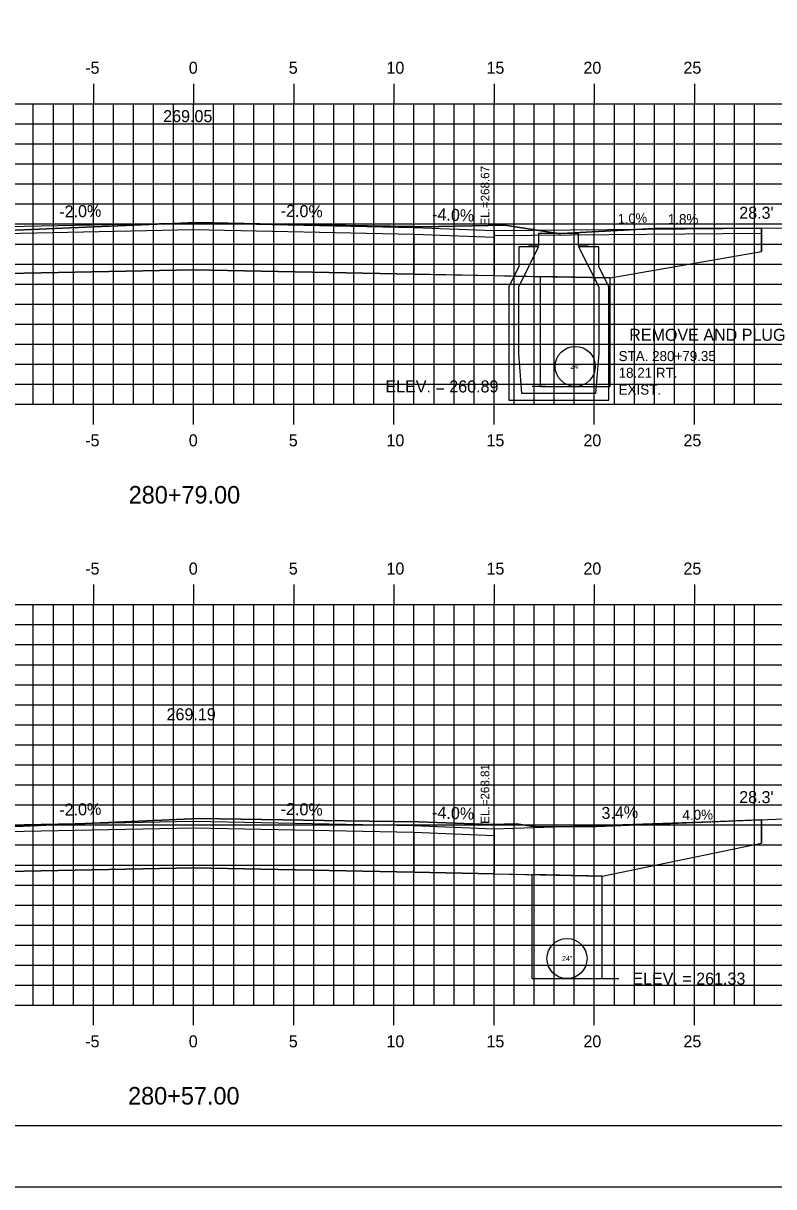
# Model space of a CAD drawing. Extents: x 855344 to 855514, y 366268 to 366378.
# Drawn here: x 855418.6 to 855456.1, y 366268.2 to 366326.3 of the extents above; entities that cross this region are included whole.
import ezdxf

# ---------------------------------------------------------------- set-up
doc = ezdxf.new("R2010")
doc.units = 0
for name, color, linetype in [('ANNOTATION', 7, 'Continuous'), ('BORDER', 7, 'Continuous'), ('D_Roadway_Centerline_Text', 7, 'Continuous'), ('D_Roadway_Drive_Gravel_RT', 7, 'Continuous'), ('D_Roadway_Drive_SubGrade', 7, 'Continuous'), ('D_Roadway_Edge_Shoulder', 7, 'Continuous'), ('D_Roadway_SubGrade', 7, 'Continuous'), ('D_Text_Monospaced', 7, 'Continuous'), ('D_Text_Standard', 7, 'Continuous'), ('H_V ANNOTATION', 7, 'Continuous'), ('JUNK COM EXC', 7, 'Continuous'), ('junk strct exc', 7, 'Continuous'), ('MAJOR', 7, 'Continuous'), ('MINOR', 7, 'Continuous'), ('PDRAIN', 7, 'Continuous'), ('PLOT BOUNDARY', 7, 'Continuous'), ('S_Drainage_CB', 7, 'Continuous'), ('S_Roadway_Centerline', 7, 'Continuous')]:
    doc.layers.add(name, color=color, linetype=linetype)

msp = doc.modelspace()

# ---------------------------------------------------------------- linework, layer by layer
at = {"layer": 'BORDER'}
msp.add_line((855352.11, 366271.236), (855512.11, 366271.236), dxfattribs=at)
at = {"layer": 'D_Roadway_Drive_Gravel_RT'}
for p, q in [((855442.11, 366315.908), (855455.458, 366316.033)), ((855442.11, 366315.658), (855455.458, 366315.783)), ((855442.107, 366286.048), (855455.456, 366286.494))]:
    msp.add_line(p, q, dxfattribs=at)
at = {"layer": 'D_Roadway_Drive_SubGrade'}
for p, q in [((855455.458, 366316.033), (855455.458, 366314.866)), ((855447.908, 366313.54), (855455.458, 366314.866)), ((855442.109, 366313.656), (855447.908, 366313.54)), ((855455.456, 366286.494), (855455.456, 366285.327)), ((855447.496, 366283.687), (855455.456, 366285.327)), ((855442.107, 366283.795), (855447.496, 366283.687))]:
    msp.add_line(p, q, dxfattribs=at)
at = {"layer": 'D_Roadway_Edge_Shoulder'}
for p, q in [((855442.107, 366315.908), (855442.11, 366315.575)), ((855442.11, 366315.908), (855442.109, 366315.576)), ((855442.107, 366286.048), (855442.11, 366285.547)), ((855442.107, 366286.048), (855442.107, 366285.715))]:
    msp.add_line(p, q, dxfattribs=at)
for points in [[(855410.364, 366315.839), (855416.11, 366316.069), (855427.11, 366316.288), (855438.11, 366316.068), (855442.107, 366315.908)], [(855408.764, 366285.915), (855416.11, 366286.208), (855427.11, 366286.428), (855438.11, 366286.208), (855442.107, 366286.048)]]:
    msp.add_lwpolyline(points, dxfattribs=at)
at = {"layer": 'D_Roadway_SubGrade'}
for points in [[(855416.11, 366313.735), (855416.11, 366315.735), (855427.11, 366315.955), (855438.11, 366315.735), (855438.11, 366313.735), (855427.11, 366313.955)], [(855438.11, 366315.735), (855442.11, 366315.575), (855442.11, 366313.655), (855438.11, 366313.735)], [(855416.11, 366283.875), (855416.11, 366285.875), (855427.11, 366286.095), (855438.11, 366285.875), (855438.11, 366283.875), (855427.11, 366284.095)], [(855438.11, 366285.875), (855442.11, 366285.715), (855442.11, 366283.795), (855438.11, 366283.875)]]:
    msp.add_lwpolyline(points, close=True, dxfattribs=at)
at = {"layer": 'D_Text_Standard'}
for points in [[(855444.408, 366308.126), (855444.687, 366308.126), (855444.007, 366308.126)], [(855447.496, 366278.566), (855447.645, 366278.566), (855448.325, 366278.566)]]:
    msp.add_lwpolyline(points, dxfattribs=at)
at = {"layer": 'JUNK COM EXC'}
for points in [[(855442.11, 366313.656), (855443.109, 366313.636), (855447.908, 366313.54), (855455.458, 366314.866), (855455.458, 366316.033), (855450.115, 366316.007), (855445.453, 366315.764), (855445.301, 366315.765), (855442.641, 366316.173), (855438.522, 366316.091), (855438.043, 366316.107), (855433.603, 366316.181), (855427.262, 366316.303), (855418.219, 366315.925), (855416.377, 366315.798), (855415.114, 366315.783), (855411.326, 366315.64), (855409.364, 366315.641), (855409.364, 366313.6), (855410.364, 366313.62), (855416.11, 366313.735), (855427.11, 366313.955), (855438.11, 366313.735), (855440.11, 366313.695)], [(855455.456, 366286.494), (855448.857, 366286.219), (855446.795, 366286.149), (855444.06, 366286.162), (855443.249, 366286.287), (855441.994, 366286.262), (855438.341, 366286.386), (855434.651, 366286.447), (855427.383, 366286.558), (855424.003, 366286.406), (855416.618, 366286.097), (855413.068, 366285.862), (855411.293, 366285.775), (855408.987, 366285.898), (855407.764, 366285.942), (855407.764, 366283.708), (855408.764, 366283.728), (855416.11, 366283.875), (855427.11, 366284.095), (855438.11, 366283.875), (855442.11, 366283.795), (855443.107, 366283.775), (855447.496, 366283.687), (855455.456, 366285.327)]]:
    msp.add_lwpolyline(points, close=True, dxfattribs=at)
at = {"layer": 'junk strct exc'}
for points in [[(855444.408, 366313.61), (855444.408, 366308.126), (855447.908, 366308.126), (855447.908, 366313.54)], [(855443.996, 366283.757), (855443.996, 366278.566), (855447.496, 366278.566), (855447.496, 366283.687)]]:
    msp.add_lwpolyline(points, close=True, dxfattribs=at)
at = {"layer": 'MAJOR'}
for p, q in [((855422.11, 366323.238), (855422.11, 366322.236)), ((855427.11, 366323.238), (855427.11, 366322.236)), ((855432.11, 366323.238), (855432.11, 366322.236)), ((855437.11, 366323.238), (855437.11, 366322.236)), ((855442.11, 366323.238), (855442.11, 366322.236)), ((855447.11, 366323.238), (855447.11, 366322.236)), ((855452.11, 366323.238), (855452.11, 366322.236)), ((855357.11, 366322.236), (855497.11, 366322.236)), ((855357.11, 366322.236), (855497.11, 366322.236)), ((855422.11, 366307.236), (855422.11, 366322.236)), ((855427.11, 366307.236), (855427.11, 366322.236)), ((855432.11, 366307.236), (855432.11, 366322.236)), ((855437.11, 366307.236), (855437.11, 366322.236)), ((855442.11, 366307.236), (855442.11, 366322.236)), ((855447.11, 366307.236), (855447.11, 366322.236)), ((855452.11, 366307.236), (855452.11, 366322.236)), ((855357.11, 366317.236), (855497.11, 366317.236)), ((855357.11, 366312.236), (855497.11, 366312.236)), ((855357.11, 366307.236), (855497.11, 366307.236)), ((855357.11, 366307.236), (855497.11, 366307.236)), ((855422.11, 366306.234), (855422.11, 366307.236)), ((855427.11, 366306.234), (855427.11, 366307.236)), ((855432.11, 366306.234), (855432.11, 366307.236)), ((855437.11, 366306.234), (855437.11, 366307.236)), ((855442.11, 366306.234), (855442.11, 366307.236)), ((855447.11, 366306.234), (855447.11, 366307.236)), ((855452.11, 366306.234), (855452.11, 366307.236)), ((855422.11, 366298.238), (855422.11, 366297.236)), ((855427.11, 366298.238), (855427.11, 366297.236)), ((855432.11, 366298.238), (855432.11, 366297.236)), ((855437.11, 366298.238), (855437.11, 366297.236)), ((855442.11, 366298.238), (855442.11, 366297.236)), ((855447.11, 366298.238), (855447.11, 366297.236)), ((855452.11, 366298.238), (855452.11, 366297.236)), ((855357.11, 366297.236), (855497.11, 366297.236)), ((855357.11, 366297.236), (855497.11, 366297.236)), ((855422.11, 366277.236), (855422.11, 366297.236)), ((855427.11, 366277.236), (855427.11, 366297.236)), ((855432.11, 366277.236), (855432.11, 366297.236)), ((855437.11, 366277.236), (855437.11, 366297.236)), ((855442.11, 366277.236), (855442.11, 366297.236)), ((855447.11, 366277.236), (855447.11, 366297.236)), ((855452.11, 366277.236), (855452.11, 366297.236)), ((855357.11, 366292.236), (855497.11, 366292.236)), ((855357.11, 366287.236), (855497.11, 366287.236)), ((855357.11, 366282.236), (855497.11, 366282.236)), ((855357.11, 366277.236), (855497.11, 366277.236)), ((855357.11, 366277.236), (855497.11, 366277.236)), ((855422.11, 366276.234), (855422.11, 366277.236)), ((855427.11, 366276.234), (855427.11, 366277.236)), ((855432.11, 366276.234), (855432.11, 366277.236)), ((855437.11, 366276.234), (855437.11, 366277.236)), ((855442.11, 366276.234), (855442.11, 366277.236)), ((855447.11, 366276.234), (855447.11, 366277.236)), ((855452.11, 366276.234), (855452.11, 366277.236))]:
    msp.add_line(p, q, dxfattribs=at)
at = {"layer": 'MINOR'}
for p, q in [((855419.11, 366307.236), (855419.11, 366322.236)), ((855420.11, 366307.236), (855420.11, 366322.236)), ((855421.11, 366307.236), (855421.11, 366322.236)), ((855423.11, 366307.236), (855423.11, 366322.236)), ((855424.11, 366307.236), (855424.11, 366322.236)), ((855425.11, 366307.236), (855425.11, 366322.236)), ((855426.11, 366307.236), (855426.11, 366322.236)), ((855428.11, 366307.236), (855428.11, 366322.236)), ((855429.11, 366307.236), (855429.11, 366322.236)), ((855430.11, 366307.236), (855430.11, 366322.236)), ((855431.11, 366307.236), (855431.11, 366322.236)), ((855433.11, 366307.236), (855433.11, 366322.236)), ((855434.11, 366307.236), (855434.11, 366322.236)), ((855435.11, 366307.236), (855435.11, 366322.236)), ((855436.11, 366307.236), (855436.11, 366322.236)), ((855438.11, 366307.236), (855438.11, 366322.236)), ((855439.11, 366307.236), (855439.11, 366322.236)), ((855440.11, 366307.236), (855440.11, 366322.236)), ((855441.11, 366307.236), (855441.11, 366322.236)), ((855443.11, 366307.236), (855443.11, 366322.236)), ((855444.11, 366307.236), (855444.11, 366322.236)), ((855445.11, 366307.236), (855445.11, 366322.236)), ((855446.11, 366307.236), (855446.11, 366322.236)), ((855448.11, 366307.236), (855448.11, 366322.236)), ((855449.11, 366307.236), (855449.11, 366322.236)), ((855450.11, 366307.236), (855450.11, 366322.236)), ((855451.11, 366307.236), (855451.11, 366322.236)), ((855453.11, 366307.236), (855453.11, 366322.236)), ((855454.11, 366307.236), (855454.11, 366322.236)), ((855455.11, 366307.236), (855455.11, 366322.236)), ((855357.11, 366321.236), (855497.11, 366321.236)), ((855357.11, 366320.236), (855497.11, 366320.236)), ((855357.11, 366319.236), (855497.11, 366319.236)), ((855357.11, 366318.236), (855497.11, 366318.236)), ((855357.11, 366316.236), (855497.11, 366316.236)), ((855357.11, 366315.236), (855497.11, 366315.236)), ((855357.11, 366314.236), (855497.11, 366314.236)), ((855357.11, 366313.236), (855497.11, 366313.236)), ((855357.11, 366311.236), (855497.11, 366311.236)), ((855357.11, 366310.236), (855497.11, 366310.236)), ((855357.11, 366309.236), (855497.11, 366309.236)), ((855357.11, 366308.236), (855497.11, 366308.236)), ((855419.11, 366277.236), (855419.11, 366297.236)), ((855420.11, 366277.236), (855420.11, 366297.236)), ((855421.11, 366277.236), (855421.11, 366297.236)), ((855423.11, 366277.236), (855423.11, 366297.236)), ((855424.11, 366277.236), (855424.11, 366297.236)), ((855425.11, 366277.236), (855425.11, 366297.236)), ((855426.11, 366277.236), (855426.11, 366297.236)), ((855428.11, 366277.236), (855428.11, 366297.236)), ((855429.11, 366277.236), (855429.11, 366297.236)), ((855430.11, 366277.236), (855430.11, 366297.236)), ((855431.11, 366277.236), (855431.11, 366297.236)), ((855433.11, 366277.236), (855433.11, 366297.236)), ((855434.11, 366277.236), (855434.11, 366297.236)), ((855435.11, 366277.236), (855435.11, 366297.236)), ((855436.11, 366277.236), (855436.11, 366297.236)), ((855438.11, 366277.236), (855438.11, 366297.236)), ((855439.11, 366277.236), (855439.11, 366297.236)), ((855440.11, 366277.236), (855440.11, 366297.236)), ((855441.11, 366277.236), (855441.11, 366297.236)), ((855443.11, 366277.236), (855443.11, 366297.236)), ((855444.11, 366277.236), (855444.11, 366297.236)), ((855445.11, 366277.236), (855445.11, 366297.236)), ((855446.11, 366277.236), (855446.11, 366297.236)), ((855448.11, 366277.236), (855448.11, 366297.236)), ((855449.11, 366277.236), (855449.11, 366297.236)), ((855450.11, 366277.236), (855450.11, 366297.236)), ((855451.11, 366277.236), (855451.11, 366297.236)), ((855453.11, 366277.236), (855453.11, 366297.236)), ((855454.11, 366277.236), (855454.11, 366297.236)), ((855455.11, 366277.236), (855455.11, 366297.236)), ((855357.11, 366296.236), (855497.11, 366296.236)), ((855357.11, 366295.236), (855497.11, 366295.236)), ((855357.11, 366294.236), (855497.11, 366294.236)), ((855357.11, 366293.236), (855497.11, 366293.236)), ((855357.11, 366291.236), (855497.11, 366291.236)), ((855357.11, 366290.236), (855497.11, 366290.236)), ((855357.11, 366289.236), (855497.11, 366289.236)), ((855357.11, 366288.236), (855497.11, 366288.236)), ((855357.11, 366286.236), (855497.11, 366286.236)), ((855357.11, 366285.236), (855497.11, 366285.236)), ((855357.11, 366284.236), (855497.11, 366284.236)), ((855357.11, 366283.236), (855497.11, 366283.236)), ((855357.11, 366281.236), (855497.11, 366281.236)), ((855357.11, 366280.236), (855497.11, 366280.236)), ((855357.11, 366279.236), (855497.11, 366279.236)), ((855357.11, 366278.236), (855497.11, 366278.236))]:
    msp.add_line(p, q, dxfattribs=at)
at = {"layer": 'PDRAIN'}
for points in [[(855444.408, 366313.61), (855444.408, 366308.126), (855447.908, 366308.126), (855447.908, 366313.54)], [(855443.996, 366283.757), (855443.996, 366278.566), (855447.496, 366278.566), (855447.496, 366283.687)]]:
    msp.add_lwpolyline(points, dxfattribs=at)
for centre in [(855446.158, 366309.126), (855445.746, 366279.566)]:
    msp.add_circle(centre, 1, dxfattribs=at)
at = {"layer": 'PLOT BOUNDARY'}
msp.add_lwpolyline([(855344.016, 366268.177), (855514.016, 366268.177), (855514.016, 366378.177), (855344.016, 366378.177)], close=True, dxfattribs=at)
at = {"layer": 'S_Drainage_CB'}
for p, q in [((855444.32, 366315.093), (855443.336, 366315.093)), ((855443.336, 366315.093), (855443.336, 366314.109)), ((855443.336, 366313.092), (855444.32, 366315.093)), ((855447.338, 366315.093), (855446.321, 366315.093)), ((855446.321, 366315.093), (855447.338, 366313.092)), ((855447.338, 366314.109), (855447.338, 366315.093)), ((855443.336, 366314.109), (855442.844, 366313.092)), ((855447.83, 366313.092), (855447.338, 366314.109)), ((855442.844, 366313.092), (855442.844, 366307.449)), ((855443.336, 366309.778), (855443.336, 366313.092)), ((855447.338, 366313.092), (855447.338, 366309.778)), ((855447.83, 366307.449), (855447.83, 366313.092)), ((855443.5, 366307.777), (855443.336, 366309.778)), ((855447.338, 366309.778), (855447.174, 366307.777)), ((855447.174, 366307.777), (855443.5, 366307.777)), ((855442.844, 366307.449), (855447.83, 366307.449))]:
    msp.add_line(p, q, dxfattribs=at)
msp.add_lwpolyline([(855446.813, 366315.135), (855446.321, 366315.135), (855446.321, 366315.758), (855444.32, 366315.758), (855444.32, 366315.135), (855443.828, 366315.135)], dxfattribs=at)
at = {"layer": 'S_Roadway_Centerline'}
for points in [[(855381.561, 366314.634), (855381.949, 366314.641), (855385.679, 366314.793), (855405.358, 366315.606), (855406.311, 366315.638), (855406.526, 366315.649), (855406.86, 366315.642), (855411.326, 366315.64), (855415.114, 366315.783), (855416.377, 366315.798), (855418.219, 366315.925), (855427.262, 366316.303), (855433.603, 366316.181), (855438.043, 366316.107), (855438.522, 366316.091), (855442.641, 366316.173), (855445.301, 366315.765), (855445.453, 366315.764), (855450.115, 366316.007), (855461.901, 366316.064), (855468.238, 366316.148), (855471.911, 366316.218), (855474.551, 366316.376)], [(855378.254, 366285.511), (855393.27, 366285.747), (855406.881, 366285.969), (855407.512, 366285.951), (855408.987, 366285.898), (855411.293, 366285.775), (855413.068, 366285.862), (855416.618, 366286.097), (855424.003, 366286.406), (855427.383, 366286.558), (855434.651, 366286.447), (855438.341, 366286.386), (855441.994, 366286.262), (855443.249, 366286.287), (855444.06, 366286.162), (855446.795, 366286.149), (855448.857, 366286.219), (855460.22, 366286.692)]]:
    msp.add_lwpolyline(points, dxfattribs=at)

# ---------------------------------------------------------------- texts
at = {"layer": 'ANNOTATION'}
for s, rotation, p in [('-2.0%', 1.14576, (855420.413, 366316.554)), ('-2.0%', 358.85424, (855431.453, 366316.601)), ('-4.0%', 357.70942, (855439.005, 366316.433)), ('-2.0%', 1.14576, (855420.413, 366286.694)), ('-2.0%', 358.85424, (855431.453, 366286.741)), ('-4.0%', 357.70949, (855439.004, 366286.573)), ('3.4%', 1.91598, (855447.474, 366286.527))]:
    msp.add_text(s, height=0.6, rotation=rotation, dxfattribs=at).set_placement(p)
msp.add_text('REMOVE AND PLUG', height=0.6, dxfattribs=at).set_placement((855448.85, 366310.404))
at = {"layer": 'D_Roadway_Centerline_Text'}
for s, p in [('269.05', (855425.593, 366321.32)), ('269.19', (855425.761, 366291.46))]:
    msp.add_text(s, height=0.6, dxfattribs=at).set_placement(p)
at = {"layer": 'D_Roadway_Drive_Gravel_RT'}
msp.add_text('1.0%', height=0.48, rotation=2.29061, dxfattribs=at).set_placement((855448.288, 366316.245))
at = {"layer": 'D_Text_Monospaced'}
for s, rotation, p in [('1.8%', 0.18128, (855450.778, 366316.227)), ('4.0%', 0.63334, (855451.512, 366286.487))]:
    msp.add_text(s, height=0.5, rotation=rotation, dxfattribs=at).set_placement(p)
for s, height, p in [('STA. 280+79.35', 0.49998, (855448.322, 366309.392)), ('18.21 RT.', 0.5, (855448.322, 366308.558)), ('EXIST. ', 0.5, (855448.322, 366307.718))]:
    msp.add_text(s, height=height, dxfattribs=at).set_placement(p)
at = {"layer": 'D_Text_Standard'}
for s, p in [(' EL.=268.67', (855441.871, 366315.993)), (' EL.=268.81', (855441.871, 366286.133))]:
    msp.add_text(s, height=0.4335, rotation=90, dxfattribs=at).set_placement(p)
for s, p in [("28.3'", (855454.343, 366316.494)), ('ELEV. = 260.89', (855436.682, 366307.826)), ("28.3'", (855454.34, 366287.328)), ('ELEV. = 261.33', (855449.005, 366278.266))]:
    msp.add_text(s, height=0.6, dxfattribs=at).set_placement(p)
at = {"layer": 'H_V ANNOTATION'}
for s, height, p in [('-5', 0.6, (855421.7, 366323.736)), ('0', 0.6, (855426.869, 366323.736)), ('5', 0.6, (855431.861, 366323.736)), ('10', 0.6, (855436.735, 366323.736)), ('15', 0.6, (855441.727, 366323.736)), ('20', 0.6, (855446.564, 366323.736)), ('25', 0.6, (855451.556, 366323.736)), ('-5', 0.6, (855421.7, 366305.136)), ('0', 0.6, (855426.869, 366305.136)), ('5', 0.6, (855431.861, 366305.136)), ('10', 0.6, (855436.735, 366305.136)), ('15', 0.6, (855441.727, 366305.136)), ('20', 0.6, (855446.564, 366305.136)), ('25', 0.6, (855451.556, 366305.136)), ('280+79.00', 0.875, (855423.871, 366302.28)), ('-5', 0.6, (855421.7, 366298.736)), ('0', 0.6, (855426.869, 366298.736)), ('5', 0.6, (855431.861, 366298.736)), ('10', 0.6, (855436.735, 366298.736)), ('15', 0.6, (855441.727, 366298.736)), ('20', 0.6, (855446.564, 366298.736)), ('25', 0.6, (855451.556, 366298.736)), ('-5', 0.6, (855421.7, 366275.136)), ('0', 0.6, (855426.869, 366275.136)), ('5', 0.6, (855431.861, 366275.136)), ('10', 0.6, (855436.735, 366275.136)), ('15', 0.6, (855441.727, 366275.136)), ('20', 0.6, (855446.564, 366275.136)), ('25', 0.6, (855451.556, 366275.136)), ('280+57.00', 0.875, (855423.84, 366272.28))]:
    msp.add_text(s, height=height, dxfattribs=at).set_placement(p)
at = {"layer": 'PDRAIN'}
for p in [(855445.916, 366309.001), (855445.504, 366279.441)]:
    msp.add_text('24"', height=0.25, dxfattribs=at).set_placement(p)
at = {"layer": 'S_Roadway_Centerline'}
for s, p in [('C', (855427.256, 366316.303)), ('L', (855427.262, 366316.296)), ('C', (855427.378, 366286.558)), ('L', (855427.383, 366286.551))]:
    msp.add_text(s, height=0.0146, dxfattribs=at).set_placement(p)

doc.saveas('drawing.dxf')
